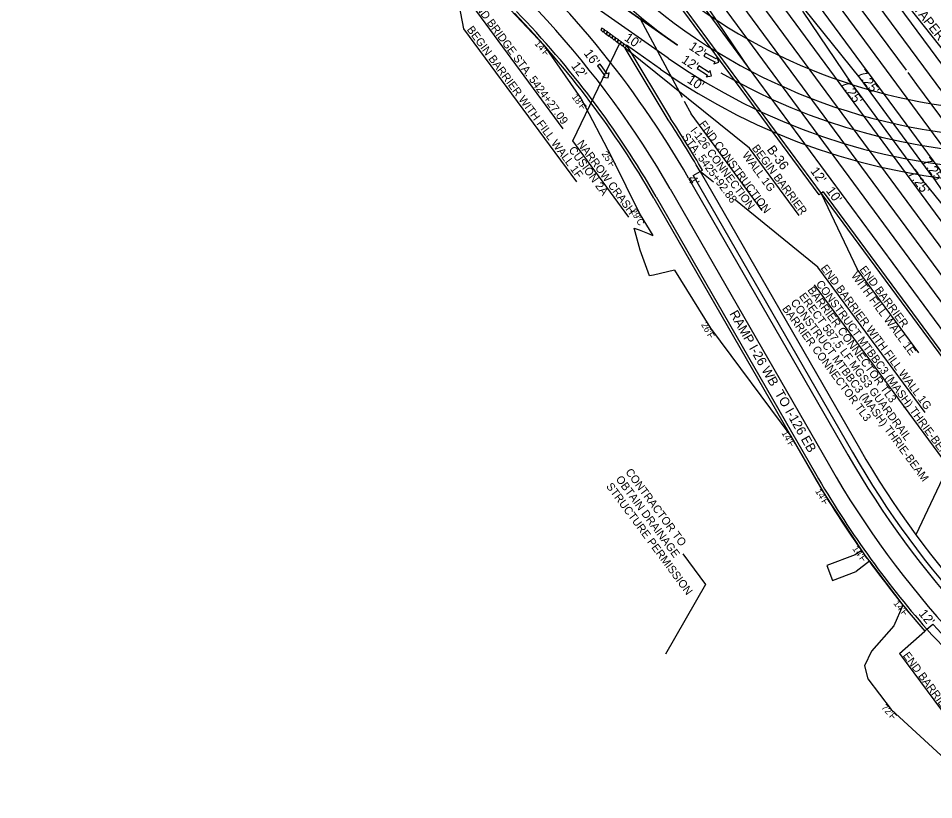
# Model space of a CAD drawing. Extents: x 1966090 to 1975830, y 788086 to 801233.
# Drawn here: x 1970458 to 1971145, y 795582 to 796167 of the extents above; entities that cross this region are included whole.
import ezdxf

# ---------------------------------------------------------------- set-up
doc = ezdxf.new("R2010")
doc.units = 0
for name, color, linetype in [('BR_PRESTRESSED BEAM', 7, 'Continuous'), ('BR_PROPOSED_DRAINAGE', 7, 'Continuous'), ('BR_REBAR', 7, 'Continuous'), ('RD_EX_Driveway_txCode', 7, 'Continuous'), ('RD_EX_RW_TX', 7, 'Continuous'), ('RD_EX_SU_Gas', 7, 'Continuous'), ('RD_EX_TX_BldgApp_ELEV', 7, 'Continuous'), ('RD_PD_PaveShd', 7, 'Continuous'), ('RD_Sketch6', 7, 'Continuous'), ('RD_Sketch8', 7, 'Continuous')]:
    doc.layers.add(name, color=color, linetype=linetype)

msp = doc.modelspace()

# ---------------------------------------------------------------- linework, layer by layer
at = {"layer": 'BR_PRESTRESSED BEAM'}
for p, q in [((1970969.59, 796052.72), (1971089.02, 795845.27)), ((1971060.28, 796036.33), (1971164.29, 795895.24))]:
    msp.add_line(p, q, dxfattribs=at)
for centre, radius, start in [((1971687.01, 796189.52), 690, 209.92814), ((1971728.37, 796249.39), 798.76, 222.51368)]:
    msp.add_arc(centre, radius, start, 235.35655, dxfattribs=at)
at = {"layer": 'BR_PROPOSED_DRAINAGE'}
for p, q in [((1970818.81, 796183), (1970852.53, 796147.43)), ((1970852.53, 796147.43), (1970880.43, 796107.1)), ((1970880.43, 796107.1), (1970903.04, 796063.67)), ((1970903.04, 796063.67), (1970924.65, 796020.22)), ((1970924.65, 796020.22), (1970934.24, 796004.79)), ((1970924.56, 795993.77), (1970920.22, 796010.27)), ((1970920.22, 796010.27), (1970923.88, 796008.92)), ((1970923.88, 796008.92), (1970930.09, 796006.41)), ((1970930.09, 796006.41), (1970934.24, 796004.79)), ((1970931.54, 795974.57), (1970924.56, 795993.77)), ((1970934.68, 795974.96), (1970931.54, 795974.57)), ((1970950.48, 795978.67), (1970934.68, 795974.96)), ((1970950.48, 795978.67), (1970977.47, 795935.25)), ((1970977.47, 795935.25), (1971037.58, 795854.46)), ((1971037.58, 795854.46), (1971062.84, 795810.95)), ((1971062.84, 795810.95), (1971090.78, 795768.32)), ((1971090.6, 795768.6), (1971085.84, 795765.45)), ((1971085.84, 795765.45), (1971064.49, 795757.34)), ((1971064.49, 795757.34), (1971068.75, 795746.12)), ((1971096.64, 795760.61), (1971086.51, 795752.86)), ((1971096.64, 795760.61), (1971121.62, 795727.75)), ((1971068.75, 795746.12), (1971086.51, 795752.86)), ((1971112.87, 795649.59), (1971153.28, 795612.29))]:
    msp.add_line(p, q, dxfattribs=at)
msp.add_lwpolyline([(1971121.62, 795727.75), (1971114.82, 795712.13), (1971098.08, 795693.17), (1971092.78, 795682.31), (1971095.31, 795672.59), (1971112.87, 795649.59)], dxfattribs=at)
at = {"layer": 'BR_REBAR'}
for p, q in [((1970712.68, 796507.84), (1971060.28, 796036.33)), ((1970937.02, 796200.16), (1971058.67, 796035.14)), ((1970914.76, 796146.82), (1970947.39, 796092.5)), ((1970945.73, 796091.4), (1970913.47, 796145.05)), ((1970971.33, 796053.72), (1970969.59, 796052.72)), ((1971060.28, 796036.33), (1971058.67, 796035.14)), ((1970934.93, 796032.77), (1971054.35, 795825.32)), ((1970936.66, 796033.77), (1971056.09, 795826.31)), ((1971138.09, 795708.29), (1971139.59, 795709.61))]:
    msp.add_line(p, q, dxfattribs=at)
for centre, radius, start, end in [((1970326.54, 795682.53), 702, 29.92814, 44.12328), ((1970326.54, 795682.53), 704, 29.92814, 44.12328), ((1970326.54, 795682.53), 742, 29.92814, 33.43783), ((1970326.54, 795682.53), 744, 29.92814, 33.43783), ((1971687.01, 796189.52), 730, 209.92814, 221.24065), ((1971687.01, 796189.52), 728, 209.92814, 221.24065)]:
    msp.add_arc(centre, radius, start, end, dxfattribs=at)
at = {"layer": 'RD_EX_Driveway_txCode'}
for points in [[(1970973.62, 796141.35), (1970972.48, 796139.24), (1970980.56, 796134.89), (1970979.79, 796133.46), (1970983.62, 796134.61), (1970982.47, 796138.44), (1970981.7, 796137.01)], [(1970894.58, 796133.18), (1970892.64, 796131.77), (1970898.05, 796124.36), (1970896.73, 796123.4), (1970900.68, 796122.78), (1970901.3, 796126.73), (1970899.98, 796125.77)], [(1970968.57, 796131.83), (1970967.3, 796129.79), (1970975.08, 796124.93), (1970974.22, 796123.55), (1970978.11, 796124.45), (1970977.21, 796128.35), (1970976.35, 796126.97)]]:
    msp.add_lwpolyline(points, close=True, dxfattribs=at)
at = {"layer": 'RD_EX_SU_Gas'}
for p, q in [((1970514.75, 796954.97), (1971123.99, 796128.55)), ((1970505.09, 796947.85), (1971239.95, 795951.02)), ((1970468.06, 796920.55), (1971202.93, 795923.73)), ((1970458.41, 796913.43), (1971193.27, 795916.61)), ((1970838.13, 796378.12), (1971016.36, 796136.35)), ((1971016.36, 796136.35), (1971183.61, 795909.49)), ((1971125.25, 796126.84), (1971131.76, 796118.01)), ((1971131.76, 796118.01), (1971249.61, 795958.14))]:
    msp.add_line(p, q, dxfattribs=at)
msp.add_arc((1971210.82, 796516.01), 450, 239.88793, 298.92325, dxfattribs=at)
at = {"layer": 'RD_EX_TX_BldgApp_ELEV'}
for p, q in [((1970895.96, 796160.07), (1970895.1, 796158.89)), ((1970898.24, 796158.86), (1970895.96, 796160.07)), ((1970895.1, 796158.89), (1970896.95, 796157.09)), ((1970896.95, 796157.09), (1970898.24, 796158.86)), ((1970898.02, 796158.57), (1970897.16, 796157.38)), ((1970897.16, 796157.38), (1970899.01, 796155.58)), ((1970900.3, 796157.36), (1970898.02, 796158.57)), ((1970899.01, 796155.58), (1970900.3, 796157.36)), ((1970900.09, 796157.06), (1970899.23, 796155.88)), ((1970899.23, 796155.88), (1970901.08, 796154.08)), ((1970902.37, 796155.85), (1970900.09, 796157.06)), ((1970901.08, 796154.08), (1970902.37, 796155.85)), ((1970902.15, 796155.56), (1970901.29, 796154.38)), ((1970901.29, 796154.38), (1970903.14, 796152.57)), ((1970904.43, 796154.35), (1970902.15, 796155.56)), ((1970903.14, 796152.57), (1970904.43, 796154.35)), ((1970904.22, 796154.05), (1970903.36, 796152.87)), ((1970903.36, 796152.87), (1970905.21, 796151.07)), ((1970906.5, 796152.84), (1970904.22, 796154.05)), ((1970905.21, 796151.07), (1970906.5, 796152.84)), ((1970906.28, 796152.55), (1970905.42, 796151.37)), ((1970905.42, 796151.37), (1970907.27, 796149.56)), ((1970905.85, 796151.96), (1970905.85, 796151.96)), ((1970908.56, 796151.34), (1970906.28, 796152.55)), ((1970907.27, 796149.56), (1970908.56, 796151.34)), ((1970908.35, 796151.04), (1970907.49, 796149.86)), ((1970907.49, 796149.86), (1970909.34, 796148.06)), ((1970910.63, 796149.83), (1970908.35, 796151.04)), ((1970909.34, 796148.06), (1970910.63, 796149.83)), ((1970910.41, 796149.54), (1970909.55, 796148.36)), ((1970909.55, 796148.36), (1970911.4, 796146.55)), ((1970912.69, 796148.33), (1970910.41, 796149.54)), ((1970911.4, 796146.55), (1970912.69, 796148.33)), ((1970912.48, 796148.03), (1970911.62, 796146.85)), ((1970911.62, 796146.85), (1970913.47, 796145.05)), ((1970914.76, 796146.82), (1970912.48, 796148.03)), ((1970913.47, 796145.05), (1970914.76, 796146.82))]:
    msp.add_line(p, q, dxfattribs=at)
at = {"layer": 'RD_PD_PaveShd'}
for p, q in [((1970712.68, 796507.84), (1971060.28, 796036.33)), ((1971089.57, 796122.57), (1971048.19, 796174.06)), ((1971083.53, 796118.12), (1971046.58, 796172.88)), ((1970940, 796129.43), (1970914.46, 796147.32)), ((1971144.16, 796048.52), (1971089.57, 796122.57)), ((1971138.13, 796044.07), (1971083.53, 796118.12)), ((1970964.39, 796049.73), (1970969.59, 796052.72)), ((1970964.39, 796049.73), (1971083.82, 795842.28)), ((1971138.13, 796044.07), (1971179.5, 795992.57)), ((1971144.16, 796048.52), (1971181.11, 795993.76)), ((1971061.89, 796037.52), (1971060.28, 796036.33)), ((1971061.89, 796037.52), (1971165.9, 795896.43)), ((1970936.66, 796033.77), (1971056.09, 795826.31)), ((1971139.59, 795709.61), (1971144.1, 795713.56))]:
    msp.add_line(p, q, dxfattribs=at)
for centre, radius, start, end in [((1971210.82, 796516.01), 418, 222.47514, 298.92325), ((1970326.54, 795682.53), 704, 29.92814, 44.12328), ((1971210.82, 796516.01), 472, 234.98689, 298.92325), ((1971687.01, 796189.52), 696, 209.92814, 235.35655), ((1971687.01, 796189.52), 728, 209.92814, 221.24065), ((1971687.01, 796189.52), 722, 221.24065, 235.35655)]:
    msp.add_arc(centre, radius, start, end, dxfattribs=at)
at = {"layer": 'RD_Sketch6'}
for p, q in [((1970792.45, 796159.71), (1970781.29, 796217.33)), ((1970866.98, 796084.66), (1970795.89, 796181.09)), ((1970924.57, 796167.1), (1970956.11, 796108.28)), ((1970877.07, 796044.93), (1970792.45, 796159.71)), ((1970874.04, 796075.63), (1970909.07, 796148.32)), ((1971006.7, 796070.1), (1970913.47, 796145.05)), ((1970957.59, 796105.51), (1970962.79, 796095.82)), ((1971016.08, 796023.53), (1970962.79, 796095.82)), ((1970916.1, 796018.59), (1970874.04, 796075.63)), ((1971043.75, 796019.84), (1971006.7, 796070.1)), ((1970979.58, 796044.61), (1970969.59, 796052.72)), ((1971060.28, 796036.33), (1971087.28, 795979.56)), ((1971057.92, 795980.99), (1970996.12, 796031.18)), ((1971138.27, 795871.99), (1971057.92, 795980.99)), ((1971133.57, 795916.77), (1971087.28, 795979.56)), ((1971055.16, 795967.79), (1971155.48, 795831.71)), ((1971155.48, 795831.71), (1971131.32, 795780.49)), ((1970956.74, 795766.18), (1970973.68, 795743.2)), ((1970973.68, 795743.2), (1970943.52, 795691.01)), ((1971119.19, 795691.4), (1971138.09, 795708.29)), ((1971119.19, 795691.4), (1971199.91, 795581.9))]:
    msp.add_line(p, q, dxfattribs=at)
at = {"layer": 'RD_Sketch8'}
for p, q in [((1970534.07, 796969.21), (1971268.93, 795972.38)), ((1970524.41, 796962.09), (1971259.27, 795965.26)), ((1970495.43, 796940.73), (1971230.29, 795943.9)), ((1970477.72, 796927.67), (1971212.58, 795930.85)), ((1970686.68, 796563.34), (1971173.95, 795902.36)), ((1970593.86, 796398.78), (1970952.62, 796147.45)), ((1970838.13, 796378.12), (1971006.7, 796129.23)), ((1971018.07, 796312.68), (1971241.34, 796030.03)), ((1970952.62, 796147.45), (1970817.21, 796242.31)), ((1970945.74, 796137.62), (1970806.83, 796234.93)), ((1970960.93, 796047.74), (1971080.35, 795840.28)), ((1970947.06, 796039.75), (1971066.49, 795832.3))]:
    msp.add_line(p, q, dxfattribs=at)
for centre, radius, start, end in [((1970326.54, 795682.53), 716, 29.92814, 54.98689), ((1971210.82, 796516.01), 438, 216.39766, 298.92325), ((1971210.82, 796516.01), 450, 216.39766, 234.98689), ((1970326.54, 795682.53), 732, 29.92814, 48.99436), ((1971210.82, 796516.01), 462, 234.98689, 298.92325), ((1971687.01, 796189.52), 700, 209.92814, 235.35655), ((1971687.01, 796189.52), 716, 209.92814, 235.35655)]:
    msp.add_arc(centre, radius, start, end, dxfattribs=at)

# ---------------------------------------------------------------- texts
at = {"layer": 'RD_EX_Driveway_txCode'}
for s, rotation, p in [('30:1 TAPER', 308.30681, (1971116.34, 796190.87)), ("10'", 326.14848, (1970912.18, 796151.36)), ("12'", 326.14848, (1970960.62, 796144.75)), ("16'", 306.13815, (1970882.01, 796141.24)), ("12'", 326.14848, (1970955.03, 796134.88)), ("12'", 306.13815, (1970872.52, 796131.79)), ("7.25'", 306.26384, (1971087.15, 796126.01)), ("10'", 326.14848, (1970959.28, 796119.82)), ("7.25'", 306.26384, (1971074.51, 796118.32)), ('B-36', 306.39762, (1971019.31, 796069.09)), ("7.25'", 306.26384, (1971135.78, 796060.05)), ("12'", 306.26384, (1971051.93, 796052.96)), ("7.25'", 306.26384, (1971125.11, 796050.99)), ("4'", 300.36763, (1970959.97, 796047.28)), ("10'", 306.26384, (1971063.67, 796038.2)), (' RAMP I-26 WB  TO I-126 EB', 299.64695, (1970990.08, 795948.44)), ("12'", 309.42927, (1971133.02, 795721.14))]:
    msp.add_text(s, height=7, rotation=rotation, dxfattribs=at).set_placement(p)
at = {"layer": 'RD_EX_RW_TX'}
for s, rotation, p in [("14'F", 311.47192, (1970845.11, 796148.28)), ("18'F", 307.47081, (1970873.09, 796108.46)), ("25'F", 303.46971, (1970895.54, 796065.94)), ("29'C", 299.92814, (1970917.12, 796023.28)), ("26'F", 299.92814, (1970970.13, 795937.98)), ("14'F", 299.92814, (1971030.47, 795856.78)), ("14'F", 301.23789, (1971055.69, 795813.1)), ("14'F", 305.239, (1971083.5, 795769.97)), ("14'F", 309.2401, (1971114.24, 795728.88)), ("72'F", 313.2412, (1971105.03, 795650.63))]:
    msp.add_text(s, height=5, rotation=rotation, dxfattribs=at).set_placement(p)
at = {"layer": 'RD_Sketch6'}
for s, height, rotation, p in [('END BRIDGE STA. 5424+27.09', 5.9996, 306.55744, (1970797.94, 796179.59)), ('BEGIN BARRIER WITH FILL WALL 1F', 5.9996, 306.55744, (1970794.38, 796159.02)), ('END CONSTRUCTION', 5.9996, 306.55916, (1970968.28, 796088.08)), ('I-126 CONNECTION', 5.9996, 306.55916, (1970961.96, 796083.39)), ('STA. 5425+92.88', 5.9996, 306.55916, (1970955.64, 796078.71)), ('CUSION 2A', 6, 306.55744, (1970870.69, 796068.81)), ('NARROW CRASH', 5.9996, 306.55744, (1970877.01, 796073.5)), ('BEGIN BARRIER', 5.9996, 306.55744, (1971008.1, 796070.16)), ('WALL 1G', 6, 306.55744, (1971000.87, 796064.8)), ('END BARRIER WITH FILL WALL 1G', 5.9996, 306.55744, (1971059.69, 795980.18)), ('END BARRIER', 5.9996, 306.55744, (1971088.83, 795979.24)), ('WITH FILL WALL 1E', 5.9996, 306.55744, (1971082.51, 795974.55)), ('CONSTRUCT MTBBC3 (MASH) THRIE-BEAM', 5.9996, 306.42425, (1971056.11, 795968.49)), ('ERECT 587.5 LF MGS3 GUARDRAIL', 5.9996, 306.42425, (1971043.45, 795959.15)), ('BARRIER CONNECTOR TL3', 5.9996, 306.42425, (1971049.78, 795963.82)), ('CONSTRUCT MTBBC3 (MASH) THRIE-BEAM', 5.9996, 306.42425, (1971037.12, 795954.48)), ('BARRIER CONNECTOR TL3', 5.9996, 306.42425, (1971030.79, 795949.81)), ('OBTAIN DRAINAGE', 5.9996, 306.5592, (1970906.05, 795822.06)), ('CONTRACTOR TO', 5.9996, 306.5592, (1970913.28, 795827.42)), ('STRUCTURE PERMISSION', 5.9996, 306.5592, (1970898.82, 795816.7)), ('END BARRIER WITH FILL WALL 1F', 5.9996, 306.55744, (1971121.29, 795689.92))]:
    msp.add_text(s, height=height, rotation=rotation, dxfattribs=at).set_placement(p)

doc.saveas('drawing.dxf')
